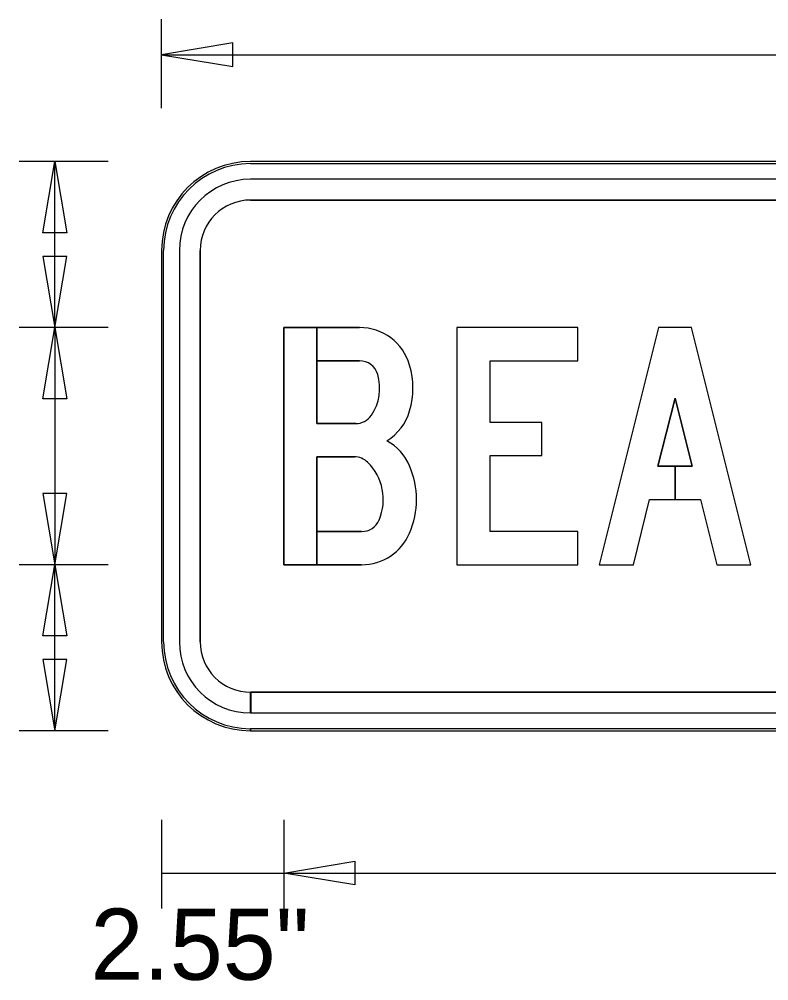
# Model space of a CAD drawing. Extents: x 57.2 to 85.4, y 153.3 to 173.4.
# Drawn here: x 64.053 to 65.369, y 159.066 to 160.756 of the extents above; entities that cross this region are included whole.
import ezdxf

# ---------------------------------------------------------------- set-up
doc = ezdxf.new("R2010")
doc.units = 0
for name, color, linetype in [('GSBWFILL', 7, 'Continuous'), ('GSCOLORFILL', 7, 'Continuous'), ('GSDIMS', 7, 'Continuous'), ('GSOUTLINE', 7, 'Continuous')]:
    doc.layers.add(name, color=color, linetype=linetype)

msp = doc.modelspace()

# ---------------------------------------------------------------- linework, layer by layer
at = {"layer": 'GSBWFILL'}
for p, q in [((68.1463, 160.5057), (64.4588, 160.5057)), ((68.1463, 160.4745), (64.4588, 160.4745)), ((64.4588, 160.438), (68.1463, 160.438)), ((64.3025, 160.3495), (64.3025, 159.6619)), ((64.3338, 160.3495), (64.3338, 159.6619)), ((64.3703, 159.6619), (64.3703, 160.3495)), ((64.4588, 159.5369), (64.4588, 159.5734)), ((68.1463, 159.5734), (64.4592, 159.5734)), ((64.4592, 159.5734), (64.4592, 159.5369)), ((64.4592, 159.5369), (68.1463, 159.5369)), ((64.4588, 159.5057), (68.1463, 159.5057))]:
    msp.add_line(p, q, dxfattribs=at)
for points in [[(64.6413, 159.9869), (64.5754, 159.9869), (64.5754, 159.7974), (64.5171, 159.7974), (64.5171, 160.214), (64.5754, 160.214), (64.5754, 160.0453), (64.6436, 160.0453)], [(64.6504, 160.1557), (64.5755, 160.1557), (64.5755, 160.214), (64.6504, 160.214)], [(64.6541, 159.7974), (64.5755, 159.7974), (64.5755, 159.8557), (64.6541, 159.8557)]]:
    msp.add_lwpolyline(points, dxfattribs=at)
for points in [[(64.8796, 159.8557), (64.8796, 159.989), (64.9709, 159.989), (64.9709, 160.0474), (64.8796, 160.0474), (64.8796, 160.1557), (65.0338, 160.1557), (65.0338, 160.214), (64.8213, 160.214), (64.8213, 159.7974), (65.0338, 159.7974), (65.0338, 159.8557)], [(65.2046, 159.9703), (65.1746, 159.9703), (65.2046, 160.0902), (65.2346, 159.9703), (65.2046, 159.9703), (65.2046, 159.9119), (65.2492, 159.9119), (65.2778, 159.7974), (65.3379, 159.7974), (65.2338, 160.214), (65.1754, 160.214), (65.0713, 159.7974), (65.1314, 159.7974), (65.16, 159.9119), (65.2046, 159.9119)]]:
    msp.add_lwpolyline(points, close=True, dxfattribs=at)
for centre, radius, start, end in [((64.4588, 160.3495), 0.1562, 90, 180), ((64.4588, 160.3495), 0.125, 90, 180), ((64.4588, 160.3495), 0.0885, 90, 180), ((64.4588, 159.6619), 0.1562, 180, 270), ((64.4588, 159.6619), 0.125, 180, 270), ((64.4588, 159.6619), 0.0885, 180, 270)]:
    msp.add_arc(centre, radius, start, end, dxfattribs=at)
for centre, major_axis, start_param, end_param in [((64.6504, 160.1224), (0, 0.0917), 4.996183, 6.283185), ((64.6504, 160.1224), (0, 0.0333), 4.996183, 6.283185), ((64.6004, 160.1078), (0, 0.0854), 4.118003, 4.996183), ((64.6004, 160.1078), (0, 0.1437), 4.428595, 4.996183), ((64.6504, 160.0932), (0, 0.0917), 3.692503, 4.428595), ((64.6436, 160.0786), (0, 0.0333), 3.141593, 4.118003), ((64.6541, 159.9349), (0, 0.0917), 5.116125, 5.778288), ((64.6413, 159.9536), (0, 0.0333), 5.507992, 6.283185), ((64.6004, 159.9119), (0, 0.0917), 4.308652, 5.507992), ((64.6004, 159.9119), (0, 0.15), 4.308653, 5.116125), ((64.6541, 159.889), (0, 0.0333), 3.141593, 4.308652), ((64.6541, 159.889), (0, 0.0917), 3.141593, 4.308652)]:
    msp.add_ellipse(centre, major_axis=major_axis, ratio=0.999993, start_param=start_param, end_param=end_param, dxfattribs=at)
at = {"layer": 'GSCOLORFILL'}
for p, q in [((68.1463, 160.5057), (64.4588, 160.5057)), ((68.1463, 160.5057), (64.4588, 160.5057)), ((64.4588, 160.5021), (68.1463, 160.5021)), ((68.1463, 160.4745), (64.4588, 160.4745)), ((64.4588, 160.438), (68.1463, 160.438)), ((64.3025, 160.3495), (64.3025, 159.6619)), ((64.3025, 160.3495), (64.3025, 159.6619)), ((64.3062, 159.6619), (64.3062, 160.3495)), ((64.3338, 160.3495), (64.3338, 159.6619)), ((64.3703, 159.6619), (64.3703, 160.3495)), ((64.4588, 159.5369), (64.4588, 159.5734)), ((68.1463, 159.5734), (64.4592, 159.5734)), ((64.4592, 159.5734), (64.4592, 159.5369)), ((64.4592, 159.5369), (68.1463, 159.5369)), ((64.4588, 159.5057), (64.4588, 159.5093)), ((68.1463, 159.5093), (64.4588, 159.5093)), ((64.4588, 159.5093), (64.4588, 159.5057)), ((64.4588, 159.5057), (68.1463, 159.5057)), ((64.4588, 159.5057), (68.1463, 159.5057))]:
    msp.add_line(p, q, dxfattribs=at)
for points in [[(64.6413, 159.9869), (64.5754, 159.9869), (64.5754, 159.7974), (64.5171, 159.7974), (64.5171, 160.214), (64.5754, 160.214), (64.5754, 160.0453), (64.6436, 160.0453)], [(64.6504, 160.1557), (64.5755, 160.1557), (64.5755, 160.214), (64.6504, 160.214)], [(64.6541, 159.7974), (64.5755, 159.7974), (64.5755, 159.8557), (64.6541, 159.8557)]]:
    msp.add_lwpolyline(points, dxfattribs=at)
for points in [[(64.8796, 159.8557), (64.8796, 159.989), (64.9709, 159.989), (64.9709, 160.0474), (64.8796, 160.0474), (64.8796, 160.1557), (65.0338, 160.1557), (65.0338, 160.214), (64.8213, 160.214), (64.8213, 159.7974), (65.0338, 159.7974), (65.0338, 159.8557)], [(65.2046, 159.9703), (65.1746, 159.9703), (65.2046, 160.0902), (65.2346, 159.9703), (65.2046, 159.9703), (65.2046, 159.9119), (65.2492, 159.9119), (65.2778, 159.7974), (65.3379, 159.7974), (65.2338, 160.214), (65.1754, 160.214), (65.0713, 159.7974), (65.1314, 159.7974), (65.16, 159.9119), (65.2046, 159.9119)]]:
    msp.add_lwpolyline(points, close=True, dxfattribs=at)
for centre, radius, start, end in [((64.4588, 160.3495), 0.1562, 90, 180), ((64.4588, 160.3495), 0.1562, 90, 180), ((64.4588, 160.3495), 0.1526, 90, 180), ((64.4588, 160.3495), 0.125, 90, 180), ((64.4588, 160.3495), 0.0885, 90, 180), ((64.4588, 159.6619), 0.1562, 180, 270), ((64.4588, 159.6619), 0.1562, 180, 270), ((64.4588, 159.6619), 0.1526, 180, 270), ((64.4588, 159.6619), 0.125, 180, 270), ((64.4588, 159.6619), 0.0885, 180, 270)]:
    msp.add_arc(centre, radius, start, end, dxfattribs=at)
for centre, major_axis, start_param, end_param in [((64.6504, 160.1224), (0, 0.0917), 4.996183, 6.283185), ((64.6504, 160.1224), (0, 0.0333), 4.996183, 6.283185), ((64.6004, 160.1078), (0, 0.0854), 4.118003, 4.996183), ((64.6004, 160.1078), (0, 0.1437), 4.428595, 4.996183), ((64.6504, 160.0932), (0, 0.0917), 3.692503, 4.428595), ((64.6436, 160.0786), (0, 0.0333), 3.141593, 4.118003), ((64.6541, 159.9349), (0, 0.0917), 5.116125, 5.778288), ((64.6413, 159.9536), (0, 0.0333), 5.507992, 6.283185), ((64.6004, 159.9119), (0, 0.0917), 4.308652, 5.507992), ((64.6004, 159.9119), (0, 0.15), 4.308653, 5.116125), ((64.6541, 159.889), (0, 0.0333), 3.141593, 4.308652), ((64.6541, 159.889), (0, 0.0917), 3.141593, 4.308652)]:
    msp.add_ellipse(centre, major_axis=major_axis, ratio=0.999993, start_param=start_param, end_param=end_param, dxfattribs=at)
at = {"layer": 'GSDIMS'}
for p, q in [((64.3025, 160.5995), (64.3025, 160.7557)), ((64.3025, 160.6932), (68.3026, 160.6932)), ((64.3025, 160.5995), (64.3025, 160.5995)), ((64.2088, 160.5057), (64.0525, 160.5057)), ((64.115, 160.214), (64.115, 160.5057)), ((64.2088, 160.214), (64.0525, 160.214)), ((64.2088, 160.214), (64.0525, 160.214)), ((64.115, 160.214), (64.115, 159.7974)), ((64.2088, 159.7974), (64.0525, 159.7974)), ((64.2088, 159.7974), (64.0525, 159.7974)), ((64.115, 159.5057), (64.115, 159.7974)), ((64.2088, 159.5057), (64.0525, 159.5057)), ((64.3025, 159.3494), (64.3025, 159.1932)), ((64.3025, 159.3494), (64.3025, 159.1932)), ((64.5171, 159.3494), (64.5171, 159.1932)), ((64.5171, 159.3494), (64.5171, 159.1932)), ((64.3025, 159.2557), (64.5171, 159.2557)), ((64.5171, 159.2557), (68.088, 159.2557))]:
    msp.add_line(p, q, dxfattribs=at)
for points in [[(64.3025, 160.6932), (64.4275, 160.6724), (64.4275, 160.7141)], [(64.115, 160.5057), (64.1359, 160.3807), (64.0942, 160.3807)], [(64.115, 160.214), (64.1359, 160.339), (64.0942, 160.339)], [(64.115, 160.214), (64.1359, 160.089), (64.0942, 160.089)], [(64.115, 159.7974), (64.1359, 159.9224), (64.0942, 159.9224)], [(64.115, 159.7974), (64.1359, 159.6724), (64.0942, 159.6724)], [(64.115, 159.5057), (64.1359, 159.6307), (64.0942, 159.6307)], [(64.5171, 159.2557), (64.6421, 159.2765), (64.6421, 159.2348)]]:
    msp.add_lwpolyline(points, close=True, dxfattribs=at)
at = {"layer": 'GSOUTLINE'}
for p, q in [((68.1463, 160.5057), (64.4588, 160.5057)), ((68.1463, 160.4745), (64.4588, 160.4745)), ((68.1463, 160.438), (64.4588, 160.438)), ((64.3025, 160.3495), (64.3025, 159.6619)), ((64.3338, 160.3495), (64.3338, 159.6619)), ((64.3703, 160.3495), (64.3703, 159.6619)), ((64.4588, 159.5734), (68.1463, 159.5734)), ((64.4588, 159.5369), (68.1463, 159.5369)), ((64.4588, 159.5057), (68.1463, 159.5057))]:
    msp.add_line(p, q, dxfattribs=at)
for points in [[(64.6504, 160.214), (64.5171, 160.214), (64.5171, 159.7974), (64.6541, 159.7974)], [(64.6436, 160.0453), (64.5754, 160.0453), (64.5754, 160.1557), (64.6504, 160.1557)], [(64.6541, 159.8557), (64.5754, 159.8557), (64.5754, 159.9869), (64.6413, 159.9869)]]:
    msp.add_lwpolyline(points, dxfattribs=at)
for points in [[(64.8796, 159.8557), (64.8796, 159.989), (64.9709, 159.989), (64.9709, 160.0474), (64.8796, 160.0474), (64.8796, 160.1557), (65.0338, 160.1557), (65.0338, 160.214), (64.8213, 160.214), (64.8213, 159.7974), (65.0338, 159.7974), (65.0338, 159.8557)], [(65.16, 159.9119), (65.2492, 159.9119), (65.2778, 159.7974), (65.3379, 159.7974), (65.2338, 160.214), (65.1754, 160.214), (65.0713, 159.7974), (65.1314, 159.7974)], [(65.2346, 159.9703), (65.2046, 160.0902), (65.1746, 159.9703)]]:
    msp.add_lwpolyline(points, close=True, dxfattribs=at)
for centre, radius, start, end in [((64.4588, 160.3495), 0.1562, 90, 180), ((64.4588, 160.3495), 0.125, 90, 180), ((64.4588, 160.3495), 0.0885, 90, 180), ((64.4588, 159.6619), 0.1562, 180, 270), ((64.4588, 159.6619), 0.125, 180, 270), ((64.4588, 159.6619), 0.0885, 180, 270)]:
    msp.add_arc(centre, radius, start, end, dxfattribs=at)
for centre, major_axis, start_param, end_param in [((64.6504, 160.1224), (0, 0.0917), 4.996183, 6.283185), ((64.6504, 160.1224), (0, 0.0333), 4.996183, 6.283185), ((64.6004, 160.1078), (0, 0.0854), 4.118003, 4.996183), ((64.6004, 160.1078), (0, 0.1437), 4.428595, 4.996183), ((64.6504, 160.0932), (0, 0.0917), 3.692503, 4.428595), ((64.6436, 160.0786), (0, 0.0333), 3.141593, 4.118003), ((64.6541, 159.9349), (0, 0.0917), 5.116125, 5.778288), ((64.6413, 159.9536), (0, 0.0333), 5.507992, 6.283185), ((64.6004, 159.9119), (0, 0.0917), 4.308652, 5.507992), ((64.6004, 159.9119), (0, 0.15), 4.308652, 5.116125), ((64.6541, 159.889), (0, 0.0333), 3.141593, 4.308652), ((64.6541, 159.889), (0, 0.0917), 3.141593, 4.308652)]:
    msp.add_ellipse(centre, major_axis=major_axis, ratio=0.999993, start_param=start_param, end_param=end_param, dxfattribs=at)

# ---------------------------------------------------------------- texts
at = {"layer": 'GSDIMS'}
msp.add_text('2.55"', height=0.125, dxfattribs=at).set_placement((64.1777, 159.0682))

doc.saveas('drawing.dxf')
